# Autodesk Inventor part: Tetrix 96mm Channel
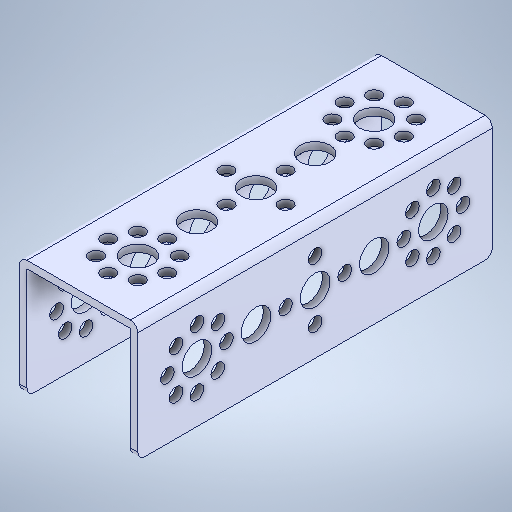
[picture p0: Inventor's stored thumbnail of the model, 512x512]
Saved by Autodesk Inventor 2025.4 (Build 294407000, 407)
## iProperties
Created: 2021-10
Part Number: Tetrix 96mm Channel
Material: Genérico
Document SubType Name: Modeling
Designer: usuario
Density: 1 g/cm^3
Appearance: Valor por defecto
Author: usuario
Sending System: SolidWorks 2016
Last Author: LENOVO
Last Saved: 2021-10-21
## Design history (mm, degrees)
fillet "Fillet1"
node "Plane1"
node "Sólido1"
